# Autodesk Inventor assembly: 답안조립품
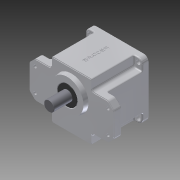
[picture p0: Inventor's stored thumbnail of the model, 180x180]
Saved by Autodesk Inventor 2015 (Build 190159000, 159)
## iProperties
Created: 2016-02
Part Number: 답안조립품
Document SubType Name: Assembly
Designer: Administrator
Mass: 1590.02 g
Surface Area: 1268.75 cm^2
Volume: 451.447 cm^3
Density: 3.52205 g/cm^3
Author: Administrator
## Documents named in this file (10)
- C:\Users\Administrator\Desktop\460209V1017\답안조립품.iam
- C:\Users\Administrator\Desktop\460209V1017\본체.ipt
- C:\Users\Administrator\Desktop\460209V1017\오일실 17 32 8.ipt
- C:\Users\Administrator\Desktop\460209V1017\커버.ipt
- C:\Users\Administrator\Desktop\460209V1017\오일실 8 22 7.ipt
- C:\Users\Administrator\Desktop\460209V1017\베어링 608.ipt
- C:\Users\Administrator\Desktop\460209V1017\메인축.ipt
- C:\Users\Administrator\Desktop\460209V1017\서브축.ipt
- C:\Users\Administrator\Desktop\460209V1017\베어링 6003.ipt
- C:\Users\Administrator\Desktop\460209V1017\볼트 M4 x 10.ipt
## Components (2 placed, 1 different names)
1. ISO 4762 M4 x 10:1 — Insert:2
2. ISO 4762 M4 x 10:2 — Insert:1
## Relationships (2: Insert 2)
- Insert:1: ISO 4762 M4 x 10:2
- Insert:2: ISO 4762 M4 x 10:1
